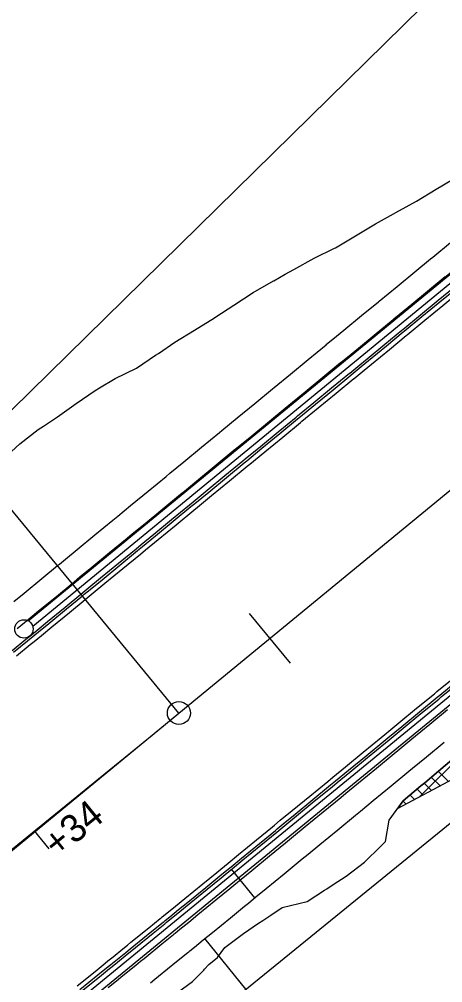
# Model space of a CAD drawing. Extents: x 1147550 to 1149124, y 2017436 to 2018779.
# Drawn here: x 1148642.9 to 1148734.8, y 2018257.9 to 2018467.3 of the extents above; entities that cross this region are included whole.
import ezdxf

# ---------------------------------------------------------------- set-up
doc = ezdxf.new("R2010")
doc.units = 0
for name, color, linetype in [('S_EDGE_CONCRETE', 7, 'Continuous'), ('S_HEADWALL', 7, 'Continuous'), ('S_IRON_PIN_ANNOT', 7, 'Continuous'), ('S_MAILBOX', 7, 'Continuous'), ('S_RDW_PT_SYM', 7, 'Continuous'), ('S_SECONDARY_CTL', 7, 'Continuous'), ('S_TELEPHONE_UTILITIES', 7, 'Continuous'), ('S_TELEPHONE_UTILITIES_ANNOT', 7, 'Continuous')]:
    doc.layers.add(name, color=color, linetype=linetype)

msp = doc.modelspace()

# ---------------------------------------------------------------- linework, layer by layer
at = {"layer": 'S_EDGE_CONCRETE'}
for p, q in [((1148677.53, 2018316.54), (1149083.36, 2018650.43)), ((1148491.47, 2018163.46), (1148677.53, 2018316.54))]:
    msp.add_line(p, q, dxfattribs=at)
msp.add_lwpolyline([(1148692.8, 2018338.16), (1148701.69, 2018327.35)], dxfattribs=at)
msp.add_circle((1148677.53, 2018316.54), 2.5, dxfattribs=at)
msp.add_arc((1145037.29, 2022741.09), 5729.58, 304.629463, 309.445337, dxfattribs=at)
at = {"layer": 'S_HEADWALL'}
for p, q in [((1148649.34, 2018287.05), (1148646.19, 2018290.93)), ((1148694.03, 2018276.39), (1148688.99, 2018282.6)), ((1148692.1, 2018256.54), (1148683.19, 2018267.53))]:
    msp.add_line(p, q, dxfattribs=at)
at = {"layer": 'S_IRON_PIN_ANNOT'}
for p, q in [((1148729.8, 2018298.31), (1148743.42, 2018311.93)), ((1148733.9, 2018303.87), (1148736.1, 2018301.67)), ((1148732.36, 2018302.58), (1148734.26, 2018300.69)), ((1148729.28, 2018300), (1148730.57, 2018298.72)), ((1148730.82, 2018301.3), (1148732.41, 2018299.7)), ((1148726.23, 2018297.4), (1148726.88, 2018296.75)), ((1148727.75, 2018298.71), (1148728.72, 2018297.74))]:
    msp.add_line(p, q, dxfattribs=at)
for points in [[(1148725.05, 2018295.78), (1148737.29, 2018302.31), (1148759.39, 2018313.93), (1148781.46, 2018325.68), (1148803.37, 2018337.66), (1148825.28, 2018349.66), (1148846.98, 2018361.91), (1148869.23, 2018375.5), (1148890.45, 2018388.71), (1148911.17, 2018402.69), (1148932.43, 2018418.55), (1148951.91, 2018434.12), (1148970.58, 2018450.61), (1148989.32, 2018467.79), (1149007.56, 2018484.84), (1149025.52, 2018502.19), (1149043.36, 2018519.65), (1149061.14, 2018537.18), (1149078.8, 2018555.13), (1149096.46, 2018572.78), (1149114.15, 2018590.39), (1149117.96, 2018594.21)], [(1148737.73, 2018307.16), (1148733.93, 2018303.9), (1148730.92, 2018301.38), (1148730.1, 2018300.69), (1148726.28, 2018297.47), (1148725.05, 2018295.78)]]:
    msp.add_lwpolyline(points, dxfattribs=at)
at = {"layer": 'S_MAILBOX'}
for points in [[(1147550.1, 2017525.89), (1147894.72, 2017801.4), (1147903.55, 2017831.14), (1148035.64, 2017933.4), (1148261.5, 2018084.85), (1148285.74, 2018084.65), (1148479.1, 2018223.18), (1148835.76, 2018573.62)], [(1147623.68, 2017436.42), (1147751.67, 2017548.43), (1147958.55, 2017704.02), (1148020.45, 2017753.36), (1148124.6, 2017828.73), (1148174.25, 2017853.51), (1148282.74, 2017941.53), (1148421.63, 2018031.39), (1148612.18, 2018197.22), (1148639.91, 2018214.06), (1148753.45, 2018306.48), (1148799.03, 2018350.69)]]:
    msp.add_lwpolyline(points, dxfattribs=at)
at = {"layer": 'S_RDW_PT_SYM'}
msp.add_lwpolyline([(1148677.53, 2018316.54), (1148601.29, 2018409.2)], dxfattribs=at)
at = {"layer": 'S_SECONDARY_CTL'}
for points in [[(1148639.32, 2018371.68), (1148643.01, 2018375.07), (1148646.95, 2018378.15), (1148648.12, 2018378.93), (1148651.13, 2018380.93), (1148655.21, 2018383.85), (1148659.38, 2018386.64), (1148660.28, 2018387.24), (1148663.72, 2018389.24), (1148668.3, 2018391.54), (1148672.48, 2018394.33), (1148673.07, 2018394.73), (1148676.66, 2018397.13), (1148680.94, 2018399.79), (1148685.24, 2018402.43), (1148685.59, 2018402.66), (1148689.45, 2018405.19), (1148693.66, 2018407.94), (1148698.06, 2018410.46), (1148698.13, 2018410.5), (1148700.64, 2018411.92), (1148702.48, 2018412.96), (1148706.91, 2018415.44), (1148711.31, 2018417.58), (1148711.54, 2018417.69), (1148715.89, 2018420.27), (1148720.21, 2018422.89), (1148724.15, 2018425.08), (1148724.68, 2018425.33), (1148729.15, 2018427.77), (1148733.44, 2018430.41), (1148736.93, 2018432.55)], [(1148676.42, 2018255.25), (1148680.5, 2018258.22), (1148682.78, 2018260.5), (1148682.93, 2018260.67), (1148683.12, 2018260.9), (1148684, 2018261.91), (1148685.9, 2018263.44), (1148687.53, 2018265.56), (1148691.54, 2018268.62), (1148694.85, 2018270.84), (1148695.74, 2018271.44), (1148697.48, 2018272.61), (1148699.94, 2018274.27), (1148705.41, 2018275.55), (1148709.19, 2018278.05), (1148709.64, 2018278.34), (1148711.06, 2018279.25), (1148713.84, 2018281.11), (1148717.83, 2018284.13), (1148721.41, 2018287.64), (1148722.4, 2018288.65), (1148723.24, 2018293.29), (1148726.28, 2018297.46), (1148730.1, 2018300.69), (1148730.92, 2018301.38), (1148733.93, 2018303.9), (1148737.73, 2018307.16)]]:
    msp.add_lwpolyline(points, dxfattribs=at)
at = {"layer": 'S_TELEPHONE_UTILITIES'}
msp.add_line((1148654.34, 2018344.72), (1148896.46, 2018543.92), dxfattribs=at)
for points in [[(1148641.65, 2018340.77), (1148643.9, 2018342.62), (1148647.73, 2018345.76), (1148651.16, 2018348.58), (1148651.57, 2018348.92), (1148652.87, 2018349.99), (1148655.43, 2018352.1), (1148659.29, 2018355.27), (1148663.15, 2018358.45), (1148664.24, 2018359.34), (1148667.02, 2018361.63), (1148670.88, 2018364.8), (1148674.74, 2018367.98), (1148675.57, 2018368.66), (1148678.6, 2018371.16), (1148682.46, 2018374.33), (1148686.32, 2018377.51), (1148686.87, 2018377.96), (1148690.18, 2018380.69), (1148694.04, 2018383.86), (1148697.9, 2018387.04), (1148698.22, 2018387.3), (1148701.77, 2018390.22), (1148705.63, 2018393.39), (1148709.49, 2018396.57), (1148709.55, 2018396.62), (1148711.74, 2018398.43), (1148713.35, 2018399.75), (1148717.21, 2018402.92), (1148720.88, 2018405.95), (1148721.07, 2018406.1), (1148724.93, 2018409.28), (1148728.79, 2018412.45), (1148732.22, 2018415.27), (1148732.66, 2018415.63), (1148736.52, 2018418.81)], [(1148642.41, 2018334.93), (1148643.22, 2018335.6), (1148644.82, 2018336.91), (1148647.07, 2018338.75), (1148650.91, 2018341.9), (1148654.34, 2018344.72), (1148654.75, 2018345.06), (1148656.04, 2018346.12), (1148658.61, 2018348.24), (1148662.47, 2018351.41), (1148666.33, 2018354.59), (1148667.41, 2018355.48), (1148670.19, 2018357.77), (1148674.05, 2018360.94), (1148677.91, 2018364.12), (1148678.74, 2018364.8), (1148681.78, 2018367.3), (1148685.64, 2018370.47), (1148689.5, 2018373.65), (1148690.05, 2018374.1), (1148693.36, 2018376.83), (1148697.22, 2018380), (1148701.08, 2018383.18), (1148701.4, 2018383.44), (1148704.94, 2018386.36), (1148708.8, 2018389.53), (1148712.67, 2018392.71), (1148712.73, 2018392.76), (1148714.92, 2018394.56), (1148716.53, 2018395.89), (1148720.39, 2018399.06), (1148724.06, 2018402.08), (1148724.25, 2018402.24), (1148728.11, 2018405.42), (1148731.97, 2018408.59), (1148735.4, 2018411.41)], [(1148641.28, 2018330.13), (1148644.31, 2018332.61), (1148645.12, 2018333.28), (1148646.72, 2018334.58), (1148648.97, 2018336.43), (1148652.81, 2018339.58), (1148656.25, 2018342.41), (1148656.65, 2018342.74), (1148657.95, 2018343.81), (1148660.51, 2018345.92), (1148664.38, 2018349.1), (1148668.24, 2018352.27), (1148669.32, 2018353.16), (1148672.1, 2018355.45), (1148675.96, 2018358.63), (1148679.82, 2018361.8), (1148680.65, 2018362.48), (1148683.68, 2018364.98), (1148687.54, 2018368.16), (1148691.4, 2018371.33), (1148691.95, 2018371.78), (1148695.27, 2018374.51), (1148699.13, 2018377.69), (1148702.99, 2018380.86), (1148703.3, 2018381.12), (1148706.85, 2018384.04), (1148710.71, 2018387.22), (1148714.57, 2018390.39), (1148714.63, 2018390.44), (1148716.83, 2018392.25), (1148718.43, 2018393.57), (1148722.29, 2018396.75), (1148725.97, 2018399.77), (1148726.15, 2018399.92), (1148730.02, 2018403.1), (1148733.88, 2018406.28), (1148737.3, 2018409.09)], [(1148641.59, 2018329.75), (1148644.62, 2018332.22), (1148645.44, 2018332.89), (1148647.03, 2018334.2), (1148649.29, 2018336.04), (1148653.13, 2018339.2), (1148656.56, 2018342.02), (1148656.97, 2018342.36), (1148658.27, 2018343.42), (1148660.83, 2018345.53), (1148664.69, 2018348.71), (1148668.55, 2018351.89), (1148669.64, 2018352.78), (1148672.42, 2018355.06), (1148676.28, 2018358.24), (1148680.14, 2018361.42), (1148680.97, 2018362.1), (1148684, 2018364.59), (1148687.86, 2018367.77), (1148691.72, 2018370.95), (1148692.27, 2018371.4), (1148695.58, 2018374.12), (1148699.44, 2018377.3), (1148703.31, 2018380.48), (1148703.62, 2018380.74), (1148707.17, 2018383.65), (1148711.03, 2018386.83), (1148714.89, 2018390.01), (1148714.95, 2018390.06), (1148717.14, 2018391.86), (1148718.75, 2018393.18), (1148722.61, 2018396.36), (1148726.28, 2018399.38), (1148726.47, 2018399.54), (1148730.33, 2018402.71), (1148734.19, 2018405.89), (1148737.62, 2018408.71)], [(1148642.23, 2018328.97), (1148645.26, 2018331.45), (1148646.07, 2018332.12), (1148647.67, 2018333.42), (1148649.92, 2018335.27), (1148653.76, 2018338.42), (1148657.2, 2018341.25), (1148657.61, 2018341.58), (1148658.9, 2018342.65), (1148661.47, 2018344.76), (1148665.33, 2018347.94), (1148669.19, 2018351.11), (1148670.27, 2018352), (1148673.05, 2018354.29), (1148676.91, 2018357.47), (1148680.77, 2018360.64), (1148681.6, 2018361.33), (1148684.63, 2018363.82), (1148688.5, 2018367), (1148692.36, 2018370.17), (1148692.91, 2018370.63), (1148696.22, 2018373.35), (1148700.08, 2018376.53), (1148703.94, 2018379.7), (1148704.26, 2018379.96), (1148707.8, 2018382.88), (1148711.66, 2018386.06), (1148715.52, 2018389.23), (1148715.59, 2018389.29), (1148717.78, 2018391.09), (1148719.39, 2018392.41), (1148723.25, 2018395.59), (1148726.92, 2018398.61), (1148727.11, 2018398.76), (1148730.97, 2018401.94), (1148734.83, 2018405.12), (1148738.26, 2018407.94)], [(1148655.4, 2018257.23), (1148659.31, 2018260.38), (1148661.55, 2018262.2), (1148662.1, 2018262.65), (1148663.22, 2018263.55), (1148665.34, 2018265.27), (1148666.34, 2018266.08), (1148667.12, 2018266.71), (1148671.03, 2018269.88), (1148673.5, 2018271.9), (1148673.68, 2018272.04), (1148673.9, 2018272.22), (1148674.93, 2018273.05), (1148676.82, 2018274.59), (1148678.82, 2018276.23), (1148682.72, 2018279.41), (1148685.78, 2018281.92), (1148686.61, 2018282.59), (1148688.22, 2018283.91), (1148690.5, 2018285.78), (1148694.39, 2018288.97), (1148697.86, 2018291.82), (1148698.27, 2018292.16), (1148699.56, 2018293.23), (1148702.13, 2018295.34), (1148705.99, 2018298.51), (1148709.85, 2018301.69), (1148710.94, 2018302.58), (1148713.71, 2018304.87), (1148717.57, 2018308.04), (1148721.44, 2018311.22), (1148722.27, 2018311.9), (1148725.3, 2018314.4), (1148729.16, 2018317.57), (1148733.02, 2018320.75), (1148733.57, 2018321.2), (1148736.88, 2018323.93)], [(1148656.02, 2018256.45), (1148659.94, 2018259.61), (1148662.18, 2018261.42), (1148662.73, 2018261.87), (1148663.85, 2018262.77), (1148665.97, 2018264.49), (1148666.97, 2018265.3), (1148667.75, 2018265.94), (1148671.66, 2018269.11), (1148674.13, 2018271.12), (1148674.31, 2018271.26), (1148674.54, 2018271.45), (1148675.56, 2018272.28), (1148677.45, 2018273.82), (1148679.46, 2018275.46), (1148683.35, 2018278.64), (1148686.42, 2018281.14), (1148687.24, 2018281.82), (1148688.86, 2018283.14), (1148691.13, 2018285.01), (1148695.02, 2018288.2), (1148698.5, 2018291.05), (1148698.9, 2018291.39), (1148700.2, 2018292.45), (1148702.77, 2018294.57), (1148706.63, 2018297.74), (1148710.49, 2018300.92), (1148711.57, 2018301.81), (1148714.35, 2018304.1), (1148718.21, 2018307.27), (1148722.07, 2018310.45), (1148722.9, 2018311.13), (1148725.93, 2018313.63), (1148729.79, 2018316.8), (1148733.65, 2018319.98), (1148734.2, 2018320.43), (1148737.52, 2018323.16)], [(1148656.34, 2018256.06), (1148660.25, 2018259.22), (1148662.49, 2018261.03), (1148663.05, 2018261.48), (1148664.16, 2018262.38), (1148666.29, 2018264.11), (1148667.29, 2018264.91), (1148668.07, 2018265.55), (1148671.97, 2018268.72), (1148674.45, 2018270.73), (1148674.63, 2018270.88), (1148674.85, 2018271.06), (1148675.87, 2018271.89), (1148677.76, 2018273.43), (1148679.77, 2018275.07), (1148683.67, 2018278.25), (1148686.73, 2018280.75), (1148687.56, 2018281.43), (1148689.17, 2018282.75), (1148691.45, 2018284.62), (1148695.34, 2018287.81), (1148698.81, 2018290.67), (1148699.22, 2018291), (1148700.52, 2018292.07), (1148703.08, 2018294.18), (1148706.94, 2018297.36), (1148710.81, 2018300.53), (1148711.89, 2018301.42), (1148714.67, 2018303.71), (1148718.53, 2018306.89), (1148722.39, 2018310.06), (1148723.22, 2018310.75), (1148726.25, 2018313.24), (1148730.11, 2018316.42), (1148733.97, 2018319.59), (1148734.52, 2018320.04), (1148737.83, 2018322.77)], [(1148662.14, 2018256.88), (1148664.38, 2018258.7), (1148664.94, 2018259.15), (1148666.05, 2018260.05), (1148668.18, 2018261.77), (1148669.18, 2018262.58), (1148669.96, 2018263.22), (1148673.86, 2018266.39), (1148676.34, 2018268.41), (1148676.52, 2018268.55), (1148676.74, 2018268.73), (1148677.77, 2018269.56), (1148679.66, 2018271.11), (1148681.67, 2018272.74), (1148685.57, 2018275.93), (1148688.63, 2018278.43), (1148689.46, 2018279.11), (1148691.07, 2018280.43), (1148693.35, 2018282.3), (1148697.24, 2018285.49), (1148700.72, 2018288.35), (1148701.13, 2018288.69), (1148702.42, 2018289.75), (1148704.99, 2018291.86), (1148708.85, 2018295.04), (1148712.71, 2018298.22), (1148713.79, 2018299.11), (1148716.57, 2018301.39), (1148720.43, 2018304.57), (1148724.29, 2018307.75), (1148725.12, 2018308.43), (1148728.16, 2018310.92), (1148732.02, 2018314.1), (1148735.88, 2018317.28)], [(1148671.33, 2018257.89), (1148672.33, 2018258.7), (1148673.11, 2018259.33), (1148677.02, 2018262.51), (1148679.5, 2018264.53), (1148679.67, 2018264.67), (1148679.9, 2018264.85), (1148680.92, 2018265.69), (1148682.82, 2018267.23), (1148684.83, 2018268.87), (1148688.73, 2018272.05), (1148691.8, 2018274.56), (1148692.63, 2018275.24), (1148694.24, 2018276.56), (1148696.52, 2018278.43), (1148700.42, 2018281.63), (1148703.9, 2018284.49), (1148704.3, 2018284.82), (1148705.6, 2018285.89), (1148708.17, 2018288), (1148712.03, 2018291.18), (1148715.89, 2018294.35), (1148716.97, 2018295.25), (1148719.75, 2018297.53), (1148723.61, 2018300.71), (1148727.47, 2018303.88), (1148728.3, 2018304.57), (1148731.33, 2018307.06), (1148735.19, 2018310.24)]]:
    msp.add_lwpolyline(points, dxfattribs=at)
at = {"layer": 'S_TELEPHONE_UTILITIES_ANNOT'}
for p, q in [((1148644.81, 2018336.58), (1148873.56, 2018524.76)), ((1148644.81, 2018336.58), (1148873.56, 2018524.76)), ((1148645.77, 2018335.43), (1148874.51, 2018523.6)), ((1148645.77, 2018335.43), (1148874.51, 2018523.6)), ((1148642.87, 2018243.65), (1148860.75, 2018422.28)), ((1148642.87, 2018243.65), (1148860.75, 2018422.28)), ((1148643.82, 2018242.49), (1148861.7, 2018421.12)), ((1148643.82, 2018242.49), (1148861.7, 2018421.12))]:
    msp.add_line(p, q, dxfattribs=at)
msp.add_circle((1148643.86, 2018334.83), 2, dxfattribs=at)

# ---------------------------------------------------------------- texts
at = {"layer": 'S_HEADWALL'}
msp.add_text('+34', height=6, rotation=39.0406, dxfattribs=at).set_placement((1148651.1, 2018284.88))

doc.saveas('drawing.dxf')
